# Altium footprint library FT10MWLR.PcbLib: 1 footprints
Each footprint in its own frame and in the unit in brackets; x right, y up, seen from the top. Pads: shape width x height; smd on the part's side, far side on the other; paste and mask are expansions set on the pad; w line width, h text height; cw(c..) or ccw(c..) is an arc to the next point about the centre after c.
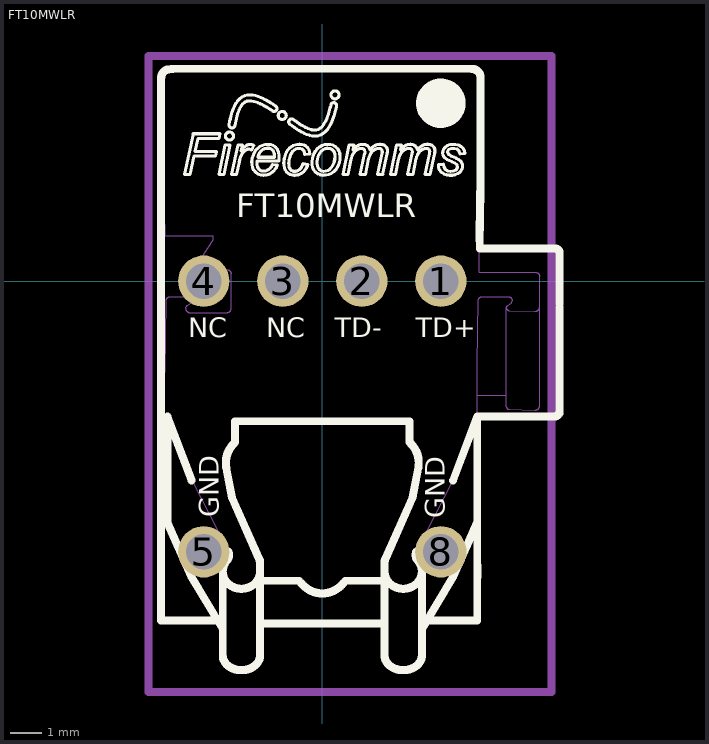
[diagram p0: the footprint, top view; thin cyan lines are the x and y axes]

## FT10MWLR [mil] "10 MBd Tilted Package Non-Inverting TTL"
height 600
pads (6):
  round 65 hole 45: 1(150,0) 2(50,0) 3(-50,0) 4(-150,0) 5(-150,-342.52) 8(150,-342.52)
Top Overlay:
  drawing of 2404 lines, arcs and shapes, not listed
  text "NC" at -169.29,-70.87 h25
  text "NC" at -70.87,-70.87 h25
  text "TD-" at 15.75,-70.87 h25
  text "TD+" at 118.11,-70.87 h25
  text "GND" at 155,-300 h25
  text "GND" at -131,-299 h25
  text "FT10MWLR" at -109,81 h30
Mechanical 2:
  lines w10: -220,-520 290,-520 290,285 -220,285 -220,-520
Mechanical 19:
  drawing of 2824 lines, arcs and shapes, not listed
3D body "Tiltet.stp": height 633.84, standoff -337.66, extent -205,-721.77 273.74,268.47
